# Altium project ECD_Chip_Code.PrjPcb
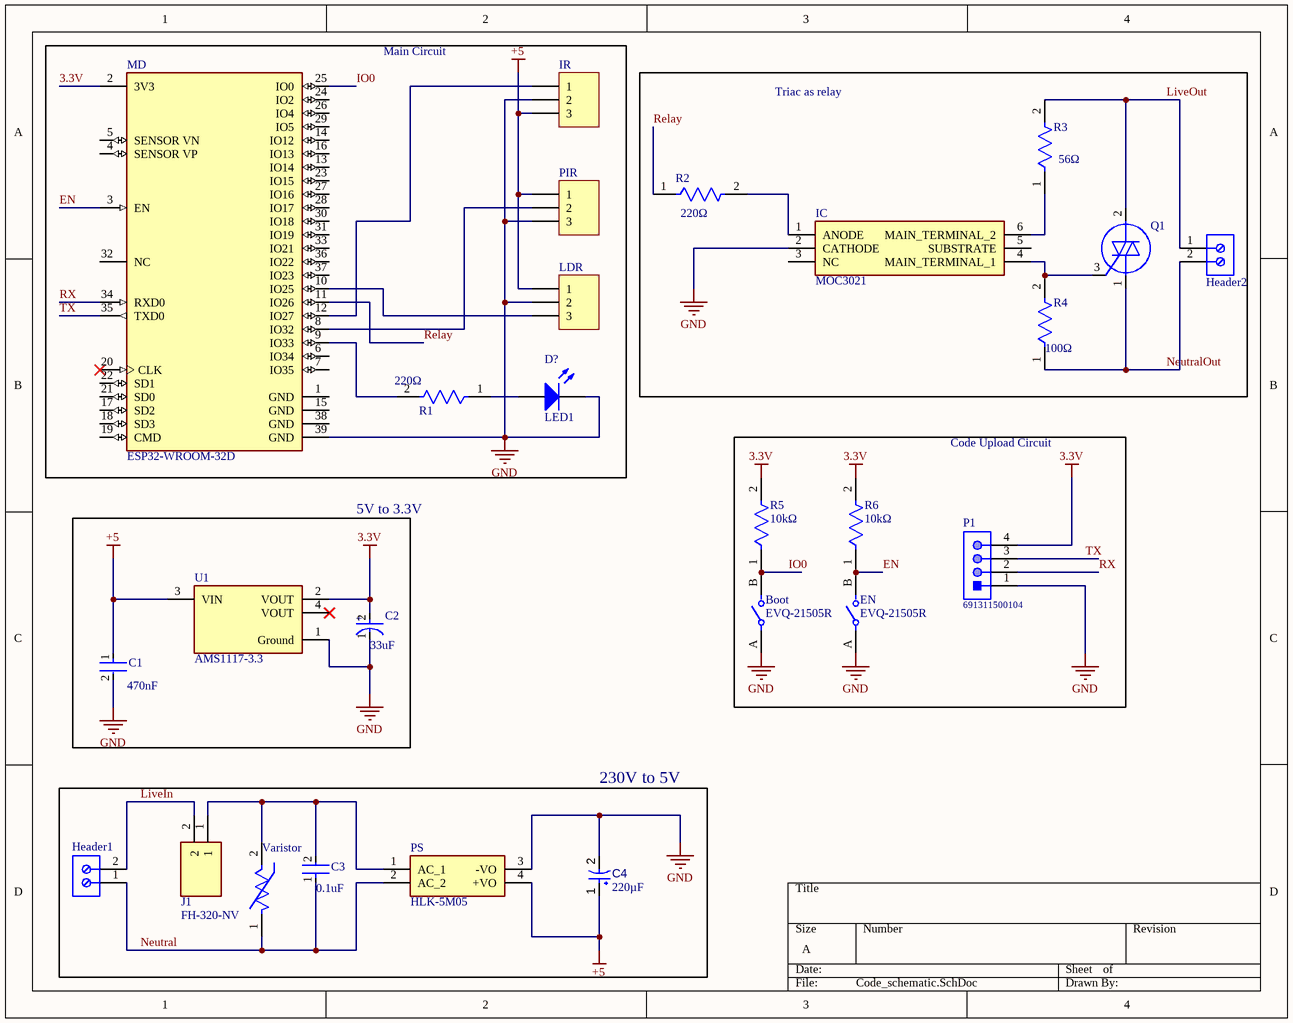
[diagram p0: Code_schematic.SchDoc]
1 sheet, 26 parts. Net scope: global (net labels, ports and power ports of the same name join across sheets).
Board file: Chip_Code_layout.PcbDoc

## Sheet Code_schematic.SchDoc
size A; SheetNumber: 1; SheetTotal: 1; SPICEModelCachePIDZZJOC: <root> / <DocumentId>PIDZZJOC</DocumentId> / <CacheFrame Number="0"> / <Model Name="led1" Kind="MDL"> / <Text>*Typ RED GaAs LED: Vf=1.7V Vr=4V If=40mA trr=3uS / *LED Pinout: 1=A, 2=K / .MODEL LED1 D (IS=93.2P RS=42M N=3.73 BV=4 IBV=10U / + CJO=2.97P VJ=.75 M=.333 TT=4.32U)</Text> / </Model> / </CacheFrame> / </root>

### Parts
Boot  EVQ-21505R  [FP-EVQ-21505R-MFG]
C1  Capacitance: 470nF  [FP-RDE4K1-MFG]  (hidden comment: RDER72E474K4M1H03A)
C2  Capacitance: 33uF  [FP-ECA-2GM330-MFG]  (hidden comment: ECA-2GM330)
C3  value 0.1uF  [FP-R46KF3100CKM1M-MFG]  (hidden comment: R46KF3100CKM1M)
C4  value 220µF  [CAPPR65-500-1250X1000X1350]  (hidden comment: ECA-1HM221)
D?  LED1  [LED-1]
EN  EVQ-21505R  [FP-EVQ-21505R-MFG]
Header1  282836-2  [TECO-282836-2_V]  (value not drawn)
Header2  282836-2  [TECO-282836-2_V]  (value not drawn)
IC  MOC3021  [DIP762W60P254L730H450Q6N]
IR  Header 3  [HDR1X3]  (value not drawn)
J1  FH-320-NV  [FH320NV]
LDR  Header 3  [HDR1X3]  (value not drawn)
MD  ESP32-WROOM-32D  [FP-ESP32-WROOM-32D-MFG]
P1  691311500104  [691311500104]
PIR  Header 3  [HDR1X3]  (value not drawn)
PS  HLK-5M05  [HLK5M05]
Q1  BT136X-600E_DG,127  [TO254P460X1000X1930-3P]  (value not drawn)
R1  value 220Ω  [FP-MBA0204-MFG]  (hidden comment: MBA02040C2200FC100)
R2  value 220Ω  [FP-MBA0204-MFG]  (hidden comment: MBA02040C2200FC100)
R3  value 56Ω  [FP-MBA0204-MFG]  (hidden comment: 56 ohm)
R4  value 100Ω  [FP-MBA0204-MFG]  (hidden comment: 100 ohm)
R5  value 10kΩ  [FP-MBA0204-MFG]  (hidden comment: 10k ohm)
R6  value 10kΩ  [FP-MBA0204-MFG]  (hidden comment: 10k ohm)
U1  AMS1117-3.3  [FP-AMS1117-IPC_C]
Varistor  MOV-14D471K  [FP-MOV-14D471K-MFG]  (value not drawn)

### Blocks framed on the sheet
Main Circuit: D? IR LDR MD PIR R1
Triac as relay: Header2 IC Q1 R2-R4
Code Upload Circuit: Boot EN P1 R5 R6
5V to 3.3V: C1 C2 U1
230V to 5V: C3 C4 Header1 J1 PS Varistor

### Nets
3.3V: C2.2(A) MD.2(3V3) P1.4 R5.2 R6.2 U1.2(VOUT)
+5: C1.1 C4.1 IR.3 LDR.1 PIR.1 PS.4(+VO) U1.3(VIN)
GND: Boot.A C1.2 C2.1(C) C4.2 D?.2(K) EN.A IC.2(CATHODE) IR.2 LDR.2 MD.39(GND) P1.1 PIR.3 PS.3(-VO) U1.1(Ground)
EN: EN.B MD.3(EN) R6.1
IO0: Boot.B MD.25(IO0) R5.1
LiveIn: Header1.2 J1.2
LiveOut: Header2.1 Q1.2(MT2) R3.2
Neutral: C3.1 Header1.1 PS.2(AC_2) Varistor.1
NeutralOut: Header2.2 Q1.1(MT1) R4.1
Relay: MD.11(IO26) R2.1
RX: MD.34(RXD0) P1.2
TX: MD.35(TXD0) P1.3
NetC3_2: C3.2 J1.1 PS.1(AC_1) Varistor.2
NetD?_1: D?.1(A) R1.1
NetIC_1: IC.1(ANODE) R2.2
NetIC_4: IC.4(MAIN_TERMINAL_1) Q1.3(G) R4.2
NetIC_6: IC.6(MAIN_TERMINAL_2) R3.1
NetIR_1: IR.1 MD.12(IO27)
NetLDR_3: LDR.3 MD.10(IO25)
NetMD_8: MD.8(IO32) PIR.2
NetMD_9: MD.9(IO33) R1.2

Not connected (* = marked no-connect by the designer): IC 3(NC) 5(SUBSTRATE); MD 1(GND) 4(SENSOR_VP) 5(SENSOR_VN) 6(IO34) 7(IO35) 13(IO14) 14(IO12) 15(GND) 16(IO13) 17(SD2) 18(SD3) 19(CMD) 20(CLK)* 21(SD0) 22(SD1) 23(IO15) 24(IO2) 26(IO4) 27(IO16) 28(IO17) 29(IO5) 30(IO18) 31(IO19) 32(NC) 33(IO21) 36(IO22) 37(IO23) 38(GND); U1 4(VOUT)*

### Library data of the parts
Boot EN = CMP-05618-000118-1: SWITCH TACTILE SPST-NO 0.02A 15V; Actuator Length: 1.6mm; Contact Current Rating: 20mA; Actuator Type: Standard; Operating Force: 1.6N; Switch Function: Off-Mom; Mechanical Life: 100000Cycles; Illumination Type: Non-Illuminated; Contact Resistance: 50mR; Actuator Color: Red; Throw Configuration: SPST; Switch Travel: 0.25mm
C1 = CMP-06035-032736-1: Ceramic Capacitor 470nF ±10% 250V X7R Radial; Lead/Base Style: Formed Leads; Lead Diameter: 0.5mm
C2 = CMP-05427-000049-1: CAP ALUM 33UF 20% 400V RADIAL; Lead Diameter: 0.8mm; Life (Hours): 2000Hour; Dissipation Factor: 0.2%; Ripple Current (AC): 275mA; Lead/Base Style: Straight
C3 = CMP-03022-000002-1: CAP FILM 0.1UF 20% 560VDC RADIAL; Manufacturer: KEMET; Voltage Rating Ac: 275V; Voltage Rating: 560V; Material: Polypropylene
C4 = CMP-001-00028-7: Aluminum Electrolytic Capacitor, 220 uF, +/- 20%, 50 V, -40 to 85 degC, 2-Pin THD, RoHS, Bulk; Manufacturer: Panasonic; Ripple Current (AC): 400mA; Voltage Rating: 50V
D? = LED1: Typical RED GaAs LED
Header1 Header2 = CMP-1684-00017-1: Female Header, Pitch 5 mm, 1 x 2 Position, Height 10 mm, Tail Length 3.5 mm, Rohs, Bulk; Manufacturer: TE Connectivity; Wire Gauge: 16-30AWG; Product Training Modules: Wire-to-BoardEurostyleTerminalBlocks; Clamp Material - Plating: Brass-NickelPlated; Voltage: 300V; Mating Orientation: HorizontalwithBoard; Current: 13.5A; Pitch: 0.197"(5.00mm); Screw Thread: M3; 3D Model: 282836-2.pdf; Other Names: 5ULV-02B / A98076; Dynamic Catalog: BuchananSeries; Number of Levels: 1; Torque - Screw: 0.68Nm(6Lb-In); Featured Product: EurostyleTerminalBlockConnectors; Positions Per Level: 2; Wire Termination: Screw-RisingCageClamp
IC = MOC3021: Integrated Circuit; Manufacturer_Name: Lite-On
IR LDR PIR = Header 3: Header, 3-Pin
J1 = FH-320-NV: Connector; Manufacturer_Name: Essentra Components
MD = CMP-194065-000003-1: WIFI MODULE 32MBITS SPI FLASH; Manufacturer: Espressif Systems; Max Supply Voltage: 3.6V; Nominal Supply Current: 500mA; Max Frequency: 2484MHz; Number Of Adc Channels: 16; Number Of Gpio: 32; Interface: I2C,SPI,UART,Ethernet,I2S,Other; Data Rate: 150Mbits/s; Min Supply Voltage: 3V; Bandwidth: 72MHz; Sensitivity: -98dBm
P1 = CMP-1502-02148-1: Serie 311 - 5.08mm Close Vertical PCB Header WR-TBL, 4 pin; Manufacturer: Wurth Elektronik; Gender: Male; Pin Number: 4
PS = HLK-5M05: Power Supply; Manufacturer_Name: Hi-Link
Q1 = BT136X-600E_DG,127: Triac; Manufacturer_Name: NXP; Manufacturer_Part_Number: BT136X-600E/DG,127
R1 R2 = CMP-02408-000005-1: RES 220 OHM 0.4W 1% AXIAL; Manufacturer: Vishay BC Components; Automotive Grade: Grade 1; Voltage Rating: 200V; Temperature Coefficient: 50ppm/°C; Power Rating: 0.25W
R3 = CMP-02408-000005-1: RES 56 OHM 0.4W 1% AXIAL; Manufacturer Part Number: MBA02040C2200FC100; Manufacturer: Vishay BC Components; Automotive Grade: Grade 1; Voltage Rating: 200V; Temperature Coefficient: 50ppm/°C; Power Rating: 0.25W
R4 = CMP-02408-000005-1: RES 100 OHM 0.4W 1% AXIAL; Manufacturer Part Number: MBA02040C2200FC100; Manufacturer: Vishay BC Components; Automotive Grade: Grade 1; Voltage Rating: 200V; Temperature Coefficient: 50ppm/°C; Power Rating: 0.25W
R5 = CMP-02408-000005-1: RES 10K OHM 0.4W 1% AXIAL; Manufacturer Part Number: MBA02040C2200FC100; Manufacturer: Vishay BC Components; Automotive Grade: Grade 1; Voltage Rating: 200V; Temperature Coefficient: 50ppm/°C; Power Rating: 0.25W
R6 = CMP-02408-000005-1: RES 10 KOHM 0.4W 1% AXIAL; Manufacturer Part Number: MBA02040C2200FC100; Manufacturer: Vishay BC Components; Automotive Grade: Grade 1; Voltage Rating: 200V; Temperature Coefficient: 50ppm/°C; Power Rating: 0.25W
U1 = CMP-209535-000001-1: LDO Voltage Regulators 1A, 3.3V; Manufacturer: Advanced Monolithic Systems; Dropout Voltage: 1.1V; Output Type: Fixed; Nominal Supply Current: 5mA; Max Power Dissipation: 1.2W; Max Supply Voltage: 15V; Number Of Outputs: 1; Standoff Height: 0.64mm; Max Junction Temp: +125°C
Varistor = CMP-07402-000007-1: VARISTOR 470V 4.5KA DISC 14MM; Manufacturer: Bourns Inc.; Value: 516pF; Clamping Voltage: 775V; Esd Protec Present: true; Voltage Rating Ac: 300V; Clamping Current: 50A; Voltage Tolerance: 10%; Varistor Voltage: 423V; Voltage Rating Dc: 385V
